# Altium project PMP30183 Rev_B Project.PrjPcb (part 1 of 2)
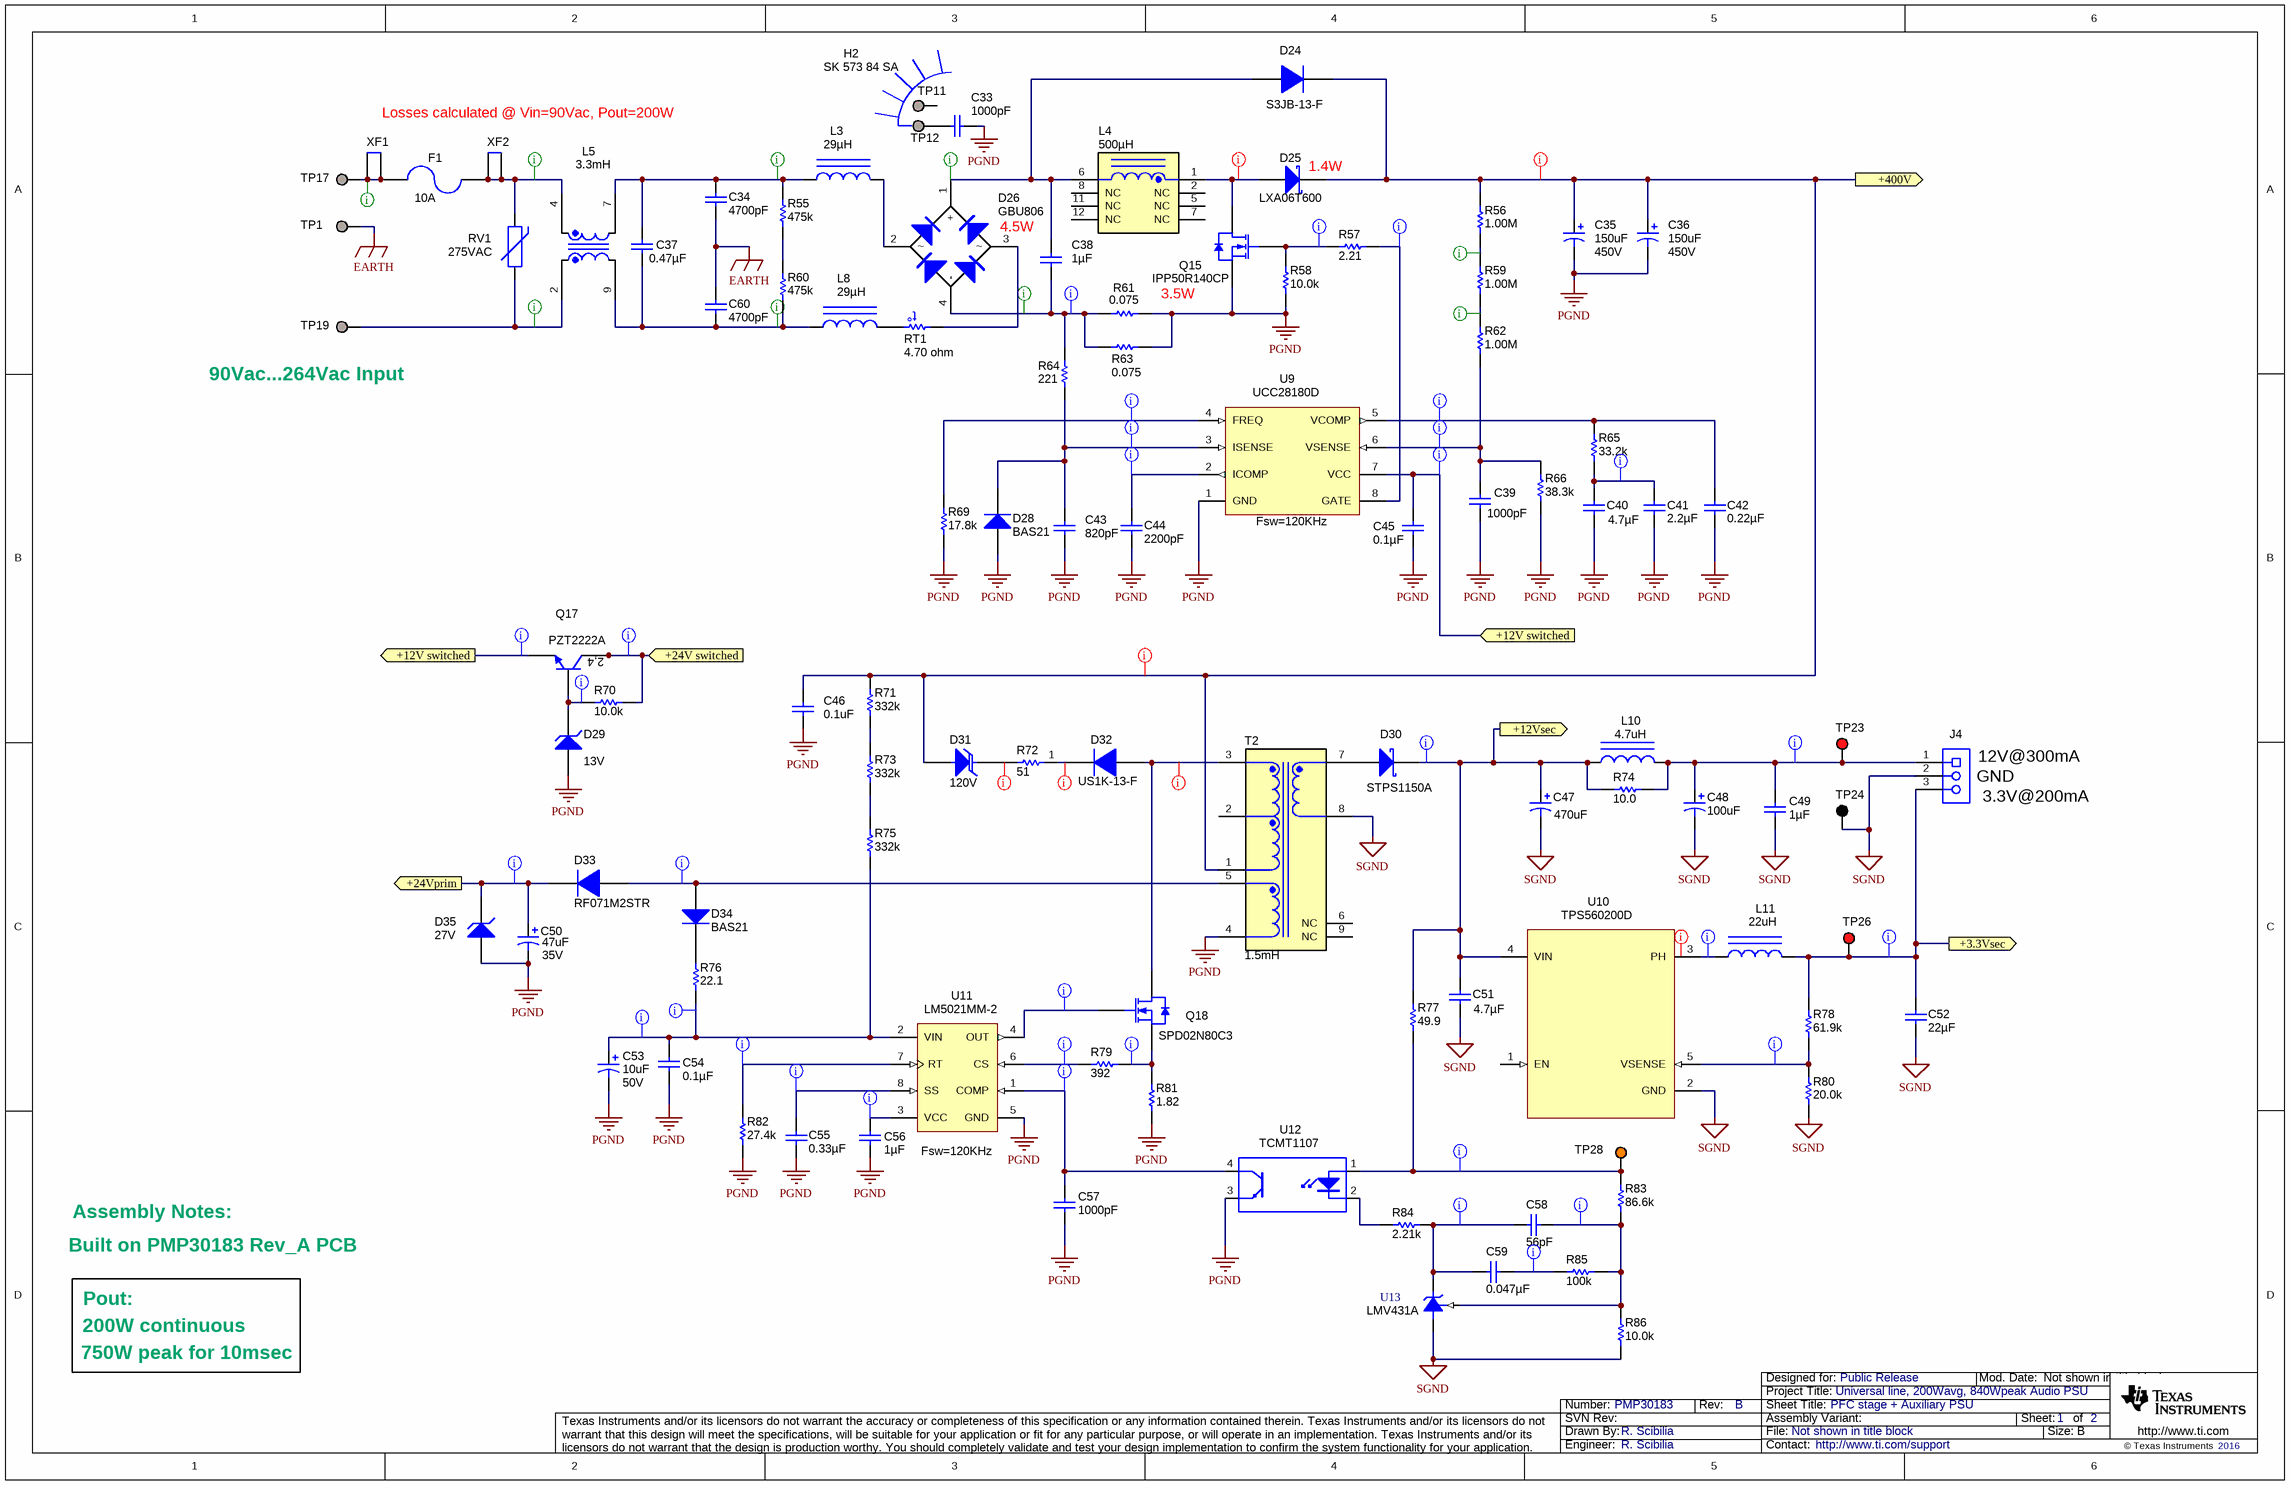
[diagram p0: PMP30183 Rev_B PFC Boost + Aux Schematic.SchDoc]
CopyrightYear: 2016; PCB_Layout: R. Scibilia; PCB_Rev: A; PRJ_Customer: Public Release; PRJ_Engineer: R. Scibilia; PRJ_Number: PMP30183; PRJ_Title: Universal line, 200Wavg, 840Wpeak Audio PSU; SCH_Rev: B; TechSupport: http://www.ti.com/support
2 sheets, 253 parts. Net scope: flat (ports and power ports of the same name join across sheets).
Board file: PMP30183 Rev_A PCB.PcbDoc
Sheets:
  PMP30183 Rev_B PFC Boost + Aux Schematic.SchDoc
  PMP30183 Rev_B 2-Switch Forward Schematic.SchDoc

## Sheet PMP30183 Rev_B PFC Boost + Aux Schematic.SchDoc: PFC stage + Auxiliary PSU
size 431 x 279 mm; Date: Not shown in title block; ApprovedBy: Not shown in title block; CheckedBy: Not shown in title block; Author: Not shown in title block; CompanyName: Not shown in title block; DrawnBy: R. Scibilia; Engineer: Not shown in title block; Organization: Not shown in title block; Address1: Not shown in title block; Address2: Not shown in title block; Address3: Not shown in title block; Address4: Not shown in title block; DocumentNumber: 2; Revision: Use project parameter SCH_Rev; SheetNumber: 1; SheetTotal: 2; PageSetup: Record=PageOptions¦CenterHorizontal=True¦CenterVertical=True¦PrintScale=0.96¦XCorrection=1.00¦YCorrection=1.00¦PrintKind=0¦BorderSize=5000000¦LeftOffset=0¦BottomOffset=0¦Orientation=2¦PaperLength=4200¦PaperWidth=2970¦Scale=100¦PaperSource=7¦PrintQuality=600¦MediaType=1¦DitherType=10¦PaperKind=A3¦PrintScaleMode=1; PRJ_Engineer: R. Scibilia; PRJ_Number: PMP30183

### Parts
C33  ValueDisplayed: 1000pF  [1206]  (hidden comment: GRM31BR72J102KW01L)
C34  ValueDisplayed: 4700pF  [VY2_1250x500x1650]  (hidden comment: VY2472M49Y5US63V7)
C35  value 150uF  Value2: 450V  [SMQ_2200X2500]  (hidden comment: 450MXK150MEFCSN22X30)
C36  value 150uF  Value2: 450V  [SMQ_2200X2500]  (hidden comment: 450MXK150MEFCSN22X30)
C37  ValueDisplayed: 0.47µF  [CAPRR2250W80L2550T850H1750]  (hidden comment: ECQ-U2A474ML)
C38  ValueDisplayed: 1µF  [CAPRR2250W80L2550T850H1750]  (hidden comment: R46KN410000P1M)
C39  ValueDisplayed: 1000pF  [0603]  (hidden comment: C1608X7R1H102K)
C40  ValueDisplayed: 4.7µF  [0805_HV]  (hidden comment: C2012X5R1E475K125AB)
C41  ValueDisplayed: 2.2µF  [0805_HV]  (hidden comment: C2012X7R1C225K)
C42  ValueDisplayed: 0.22µF  [0603]  (hidden comment: C1608X7R1C224K)
C43  ValueDisplayed: 820pF  [0603]  (hidden comment: C1608C0G1H821J)
C44  ValueDisplayed: 2200pF  [0603]  (hidden comment: C1608X7R1H222K)
C45  ValueDisplayed: 0.1µF  [0603]  (hidden comment: C1608X7R1H104K)
C46  value 0.1uF  [1210]  (hidden comment: C3225X7T2J104K160AC)
C47  value 470uF  [CAPPR3p5-8x16]  (hidden comment: EKZM160ELL471MHB5D)
C48  value 100uF  [ML_500x500]  (hidden comment: EKZM160ELL101ME11D)
C49  ValueDisplayed: 1µF  [0603]  (hidden comment: C1608X7R1C105K)
C50  value 47uF  Value2: 35V  [ZL_630x1100]  (hidden comment: UPW1V470MED1TD)
C51  ValueDisplayed: 4.7µF  [0805_HV]  (hidden comment: C2012X5R1E475K125AB)
C52  ValueDisplayed: 22µF  [0805_HV]  (hidden comment: C2012X5R0J226M)
C53  value 10uF  Value2: 50V  [ZLJ_500x1100]  (hidden comment: UPW1H100MDD)
C54  ValueDisplayed: 0.1µF  [0603]  (hidden comment: C1608X7R1H104K)
C55  ValueDisplayed: 0.33µF  [0603]  (hidden comment: C0603C334K4RACTU)
C56  ValueDisplayed: 1µF  [0603]  (hidden comment: C1608X7R1C105K)
C57  ValueDisplayed: 1000pF  [0603]  (hidden comment: C1608X7R1H102K)
C58  ValueDisplayed: 56pF  [0603]  (hidden comment: C1608C0G1H560J)
C59  ValueDisplayed: 0.047µF  [0603]  (hidden comment: C1608X8R1H473K)
C60  ValueDisplayed: 4700pF  [VY2_1250x500x1650]  (hidden comment: VY2472M49Y5US63V7)
D24  S3JB-13-F  [SMB]
D25  LXA06T600  [TO-220-F2]
D26  GBU806  [GBU]
D28  value BAS21  [SOT-23]  (hidden comment: BAS21-7-F)
D29  value 13V  [sod-323]  (hidden comment: MMSZ5243BS-7-F)
D30  STPS1150A  [SMA]
D31  value 120V  [SMA]  (hidden comment: SMAJ120A)
D32  US1K-13-F  [SMA]
D33  RF071M2STR  [SOD-123]
D34  value BAS21  [SOT-23]  (hidden comment: BAS21-7-F)
D35  value 27V  [SOD-123]  (hidden comment: MMSZ4711-T1G)
F1  value 10A  (hidden comment: 0216010.MXP)
H2  SK 573 84 SA  [FE_SK573_84]
J4  39357-0003  [Molex_39357-0003]  (value not drawn)
L3  ValueDisplayed: 29µH  [WE-FI_1900x1050]  (hidden comment: 7447016)
L4  ValueDisplayed: 500µH  [750316373]  (hidden comment: 750316373)
L5  value 3.3mH  [IND_WE-CMB_L]  (hidden comment: 744824433)
L8  ValueDisplayed: 29µH  [WE-FI_1900x1050]  (hidden comment: 7447016)
L10  value 4.7uH  [WE-PD2-S]  (hidden comment: 744773047)
L11  value 22uH  [WE-SPC_4838]  (hidden comment: 74408943220)
Q15  IPP50R140CP  [TO-220AB]
Q17  PZT2222A  [SOT-223]
Q18  value SPD02N80C3  [DPAK]  (hidden comment: SPD02N80C3ATMA1)
R55  ValueDisplayed: 475k  [1206]  (hidden comment: RC1206FR-07475KL)
R56  ValueDisplayed: 1.00M  [1206]  (hidden comment: CRCW12061M00FKEA)
R57  value 2.21  [0805_HV]  (hidden comment: CRCW08052R21FKEA)
R58  value 10.0k  [0603]  (hidden comment: CRCW060310K0FKEA)
R59  ValueDisplayed: 1.00M  [1206]  (hidden comment: CRCW12061M00FKEA)
R60  ValueDisplayed: 475k  [1206]  (hidden comment: RC1206FR-07475KL)
R61  ValueDisplayed: 0.075  [2512]  (hidden comment: CSRN2512FK75L0)
R62  ValueDisplayed: 1.00M  [1206]  (hidden comment: CRCW12061M00FKEA)
R63  ValueDisplayed: 0.075  [2512]  (hidden comment: CSRN2512FK75L0)
R64  value 221  [0603]  (hidden comment: CRCW0603221RFKEA)
R65  ValueDisplayed: 33.2k  [0603]  (hidden comment: CRCW060333K2FKEA)
R66  ValueDisplayed: 38.3k  [0603]  (hidden comment: CRCW060338K3FKEA)
R69  ValueDisplayed: 17.8k  [0603]  (hidden comment: CRCW060317K8FKEA)
R70  value 10.0k  [0603]  (hidden comment: CRCW060310K0FKEA)
R71  value 332k  [1206]  (hidden comment: CRCW1206332KFKEA)
R72  value 51  [0805_HV]  (hidden comment: CRCW080551R0JNEA)
R73  value 332k  [1206]  (hidden comment: CRCW1206332KFKEA)
R74  ValueDisplayed: 10.0  [0603]  (hidden comment: CRCW060310R0FKEA)
R75  value 332k  [1206]  (hidden comment: CRCW1206332KFKEA)
R76  ValueDisplayed: 22.1  [0603]  (hidden comment: CRCW060322R1FKEA)
R77  value 49.9  [0603]  (hidden comment: CRCW060349R9FKEA)
R78  ValueDisplayed: 61.9k  [0603]  (hidden comment: CRCW060361K9FKEA)
R79  ValueDisplayed: 392  [0603]  (hidden comment: CRCW0603392RFKEA)
R80  ValueDisplayed: 20.0k  [0603]  (hidden comment: CRCW060320K0FKEA)
R81  ValueDisplayed: 1.82  [1206]  (hidden comment: CRCW12061R82FKEA)
R82  ValueDisplayed: 27.4k  [0603]  (hidden comment: CRCW060327K4FKEA)
R83  ValueDisplayed: 86.6k  [0603]  (hidden comment: CRCW060386K6FKEA)
R84  value 2.21k  [0603]  (hidden comment: CRCW06032K21FKEA)
R85  ValueDisplayed: 100k  [0603]  (hidden comment: CRCW0603100KFKEA)
R86  value 10.0k  [0603]  (hidden comment: CRCW060310K0FKEA)
RT1  value 4.70 ohm  [S237]  (hidden comment: B57237S0479M000)
RV1  value 275VAC  [Epcos_B72220S0271K101]  (hidden comment: B72220S0271K101)
T2  ValueDisplayed: 1.5mH  [Wurth_7508110338]  (hidden comment: 7508110338)
TP1  TESTPOINT  [PAD_115mil-80milhole]  (value not drawn)  (no BOM)
TP11  TESTPOINT  [PAD_115mil-80milhole]  (value not drawn)  (no BOM)
TP12  TESTPOINT  [PAD_115mil-80milhole]  (value not drawn)  (no BOM)
TP17  TESTPOINT  [PAD_115mil-80milhole]  (value not drawn)  (no BOM)
TP19  TESTPOINT  [PAD_115mil-80milhole]  (value not drawn)  (no BOM)
TP23  5000  [Keystone5000]  (value not drawn)
TP24  5001  [Keystone5001]  (value not drawn)
TP26  5000  [Keystone5000]  (value not drawn)
TP28  5003  [Keystone5003]  (value not drawn)
U9  UCC28180D  [D0008A_N]
U10  value TPS560200D  [DBV0005A_N]  (hidden comment: TPS560200DBVR)
U11  value LM5021MM-2  [MUA08A_N]  (hidden comment: LM5021MMX-2)
U12  TCMT1107  [SOP-4]
U13  value LMV431A  [MF03A_N]  (hidden comment: LMV431BIMFX)
XF1  01000056Z  [Littelfuse_0100-0020_54_56]  (value not drawn)
XF2  01000056Z  [Littelfuse_0100-0020_54_56]  (value not drawn)

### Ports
+3.3Vsec, +12V switched, +12Vsec, +24V switched, +24Vprim, +400V

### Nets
EARTH: C34.1 C60.2 TP1.1
PGND: C33.1 C35.2(-) C36.2(-) C39.2 C40.2 C41.2 C42.2 C43.2 C44.2 C45.2 C46.2 C50.2(-) C53.2(-) C54.2 C55.2 C56.2 C57.2 D28.1(A) D29.2(A) D35.2(A) Q15.3(S) R58.1 R61.2 R63.2 R66.1 R69.1 R81.1 R82.1 T2.4 U9.1(GND) U11.5(GND) U12.3(E)
SGND: C47.2(-) C48.2(-) C49.2 C51.2 C52.2 J4.2 R80.1 R86.1 T2.8 TP24.1 U10.2(GND) U13.3(A)
+3.3Vsec: C52.1 J4.3 L11.2 R78.2 TP26.1 ; port +3.3Vsec
+12V switched: C45.1 Q17.3(E) U9.7(VCC) ; port +12V switched
+12Vsec: C47.1(+) C51.1 D30.1(K) L10.1 R74.1 R77.2 U10.4(VIN) ; port +12Vsec
+24V switched: Q17.2(C) Q17.4(C) R70.1 ; port +24V switched
+24Vprim: C50.1(+) D33.1(K) D35.1(K) ; port +24Vprim
+400V: C35.1(+) C36.1(+) C46.1 D24.1(K) D25.1(K) D31.2(A) R56.2 R71.2 T2.1 ; port +400V
NetC33_2: C33.2 TP12.1
NetC34_2: C34.2 C37.1 L3.1 L5.7 R55.2
NetC37_2: C37.2 C60.1 L5.9 L8.1 R60.1
NetC38_1: C38.1 D24.2(A) D26.1(+) L4.6
NetC38_2: C38.2 D26.4(-) R61.1 R63.1 R64.2
NetC39_1: C39.1 R62.1 R66.2 U9.6(VSENSE)
NetC40_1: C40.1 C41.1 R65.1
NetC42_1: C42.1 R65.2 U9.5(VCOMP)
NetC43_1: C43.1 D28.3(K) R64.1 U9.3(ISENSE)
NetC44_1: C44.1 U9.2(ICOMP)
NetC48_1: C48.1(+) C49.1 J4.1 L10.2 R74.2 TP23.1
NetC53_1: C53.1(+) C54.1 R75.1 R76.2 U11.2(VIN)
NetC55_1: C55.1 U11.8(SS)
NetC56_1: C56.1 U11.3(VCC)
NetC57_1: C57.1 U11.1(COMP) U12.4(C)
NetC58_1: C58.1 R83.1 R85.1 R86.2 U13.1(REF)
NetC58_2: C58.2 C59.2 R84.1 U13.2(K)
NetC59_1: C59.1 R85.2
NetD25_2: D25.2(A) L4.1 Q15.2(D)
NetD26_2: D26.2 L3.2
NetD26_3: D26.3 RT1.1
NetD29_1: D29.1(K) Q17.1(B) R70.2
NetD30_2: D30.2(A) T2.7
NetD31_1: D31.1(K) R72.2
NetD32_1: D32.1(K) R72.1
NetD32_2: D32.2(A) Q18.4(D) T2.3
NetD33_2: D33.2(A) D34.1(A) T2.5
NetD34_3: D34.3(K) R76.1
NetF1_1: F1.1 L5.4 RV1.2 XF2.1 XF2.2
NetF1_2: F1.2 TP17.1 XF1.1 XF1.2
NetL5_2: L5.2 RV1.1 TP19.1
NetL8_2: L8.2 RT1.2
NetL11_1: L11.1 U10.3(PH)
NetQ15_1: Q15.1(G) R57.1 R58.2
NetQ18_1: Q18.1(G) U11.4(OUT)
NetQ18_3: Q18.3(S) R79.2 R81.2
NetR55_1: R55.1 R60.2
NetR56_1: R56.1 R59.2
NetR57_2: R57.2 U9.8(GATE)
NetR59_1: R59.1 R62.2
NetR69_2: R69.2 U9.4(FREQ)
NetR71_1: R71.1 R73.2
NetR73_1: R73.1 R75.2
NetR77_1: R77.1 R83.2 TP28.1 U12.1(A)
NetR78_1: R78.1 R80.2 U10.5(VSENSE)
NetR79_1: R79.1 U11.6(CS)
NetR82_2: R82.2 U11.7(RT)
NetR84_2: R84.2 U12.2(K)

Not connected (* = marked no-connect by the designer): L4 2(NC) 5(NC) 7(NC) 8(NC) 11(NC) 12(NC); T2 2 6(NC) 9(NC); TP11 1; U10 1(EN)

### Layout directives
rule Undefined; rule Clearance Constraint [Clearance = 30mil]: +400V, NetD25_2, NetD31_1, NetD32_1, NetD32_2
rule Undefined; rule Clearance Constraint [Clearance = 10mil]: (no net found under the mark), +3.3Vsec, +12V switched, +12Vsec, +24V switched, +24Vprim, NetC38_2, NetC39_1, NetC40_1, NetC42_1, NetC43_1, NetC44_1, NetC48_1, NetC53_1, NetC55_1, NetC56_1, NetC57_1, NetC58_1, NetC58_2, NetC59_1, NetD29_1, NetD33_2, NetL11_1, NetQ15_1, NetQ18_1, NetQ18_3, NetR57_2, NetR69_2, NetR77_1, NetR78_1, NetR79_1, NetR82_2
rule Undefined; rule Clearance Constraint [Clearance = 20mil]: NetC34_2, NetC37_2, NetC38_1, NetC38_2, NetF1_1, NetF1_2, NetL5_2, NetR56_1, NetR59_1

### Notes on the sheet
- Losses calculated @ Vin=90Vac, Pout=200W
- (near D25) 1.4W
- (near D26) 4.5W
- (near R61) 3.5W
- (near TP19) 90Vac...264Vac Input
- (near U9) Fsw=120KHz
- (near J4) 12V@300mA
- (near J4) GND
- (near J4) 3.3V@200mA
- (near U11) Fsw=120KHz
- Assembly Notes:
- Built on PMP30183 Rev_A PCB
- Pout:
- 200W continuous
- 750W peak for 10msec

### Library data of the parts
C33 = GRM31BR72J102KW01L: CAP, CERM, 1000 pF, 630 V, +/- 10%, X7R, 1206; Manufacturer: MuRata; Polarized: N; CompType: Capacitor; Value: 1000pF; U/M: EA; Cap_F: 0.000000001; Tolerance_%: 10; Value1: Unknown; VDC_V: 630; Value2: 630V; TaMin_C: -55; TaMax_C: 125; SizeArea_mm2: 5.12; SizeAreaWB_mm2: 10.92; SizeX_mm: 3.2; SizeY_mm: 1.6; SizeZ_mm: 1.35; AEC Category: Q200
C34 C60 = VY2472M49Y5US63V7: CAP, CERM, 4700 pF, 440 V, +/- 20%, Y5U, TH, 12.5x5mm; Manufacturer: Vishay-Bccomponents; Polarized: N; CompType: Capacitor; Value: 4700pF; U/M: EA; Cap_F: 0.0000000047; Tolerance_%: 20; Value1: Unknown; VDC_V: 440; Value2: 440V; TaMin_C: -40; TaMax_C: 125; Cap_Case: 12.5x5x16.5
C35 C36 = ESMQ451VSN101MP25S: CAP, AL, 150 µF, 450 V, +/- 20%, TH; Manufacturer: Rubycon; Polarized: Y; CompType: Capacitor; ValueDisplayed: 150µF; U/M: EA; Cap_F: 0.00015; Tolerance_%: 20; Value1: Unknown; VDC_V: 450; IRMS_A: 1.12; TaMin_C: -25; TaMax_C: 105; Cap_Case: 22x25; AEC Category: Q200
C37 = ECQ-U2A474ML: CAP, Film, 0.47 µF, 275 V, +/- 20%, TH; Manufacturer: Panasonic; Polarized: N; CompType: Capacitor; Value: 0.47uF; U/M: EA; Cap_F: 0.00000047; Tolerance_%: 20; Value1: Unknown; VDC_V: 275; Value2: 275V; TaMin_C: -40; TaMax_C: 100; Cap_Case: Radial 25x8.5x18.5
C38 = ECQ-U2A474ML: CAP, Film, 1 µF, 275 V, +/- 20%, TH; Manufacturer: Kemet; Polarized: N; CompType: Capacitor; Value: 1uF; U/M: EA; Cap_F: 0.00000047; Tolerance_%: 20; Value1: Unknown; VDC_V: 275; Value2: 275V; TaMin_C: -40; TaMax_C: 100; Cap_Case: Radial 25x8.5x18.5
C39 C57 = C1608X7R1H102K: CAP, CERM, 1000 pF, 50 V, +/- 10%, X7R, 0603; Manufacturer: TDK; Polarized: N; CompType: Capacitor; Value: 1000pF; U/M: EA; Cap_F: 0.000000001; Tolerance_%: 10; ESR_ohm: 0.24; Value1: 0.24 ohm; VDC_V: 50; Value2: 50V; TaMin_C: -55; TaMax_C: 125
C40 C51 = C2012X5R1E475K125AB: CAP, CERM, 4.7 µF, 25 V, +/- 10%, X5R, 0805; Manufacturer: TDK; Polarized: N; CompType: Capacitor; Value: 4.7uF; U/M: EA; Cap_F: 0.0000047; Tolerance_%: 10; Value1: Unknown; VDC_V: 25; Value2: 25V; TaMin_C: -55; TaMax_C: 85; Cap_Case: 0805
C41 = C2012X7R1C225K: CAP, CERM, 2.2 µF, 16 V, +/- 10%, X7R, 0805; Manufacturer: TDK; Polarized: N; CompType: Capacitor; Value: 2.2uF; U/M: EA; Cap_F: 0.0000022; Tolerance_%: 10; ESR_ohm: 0.0049; Value1: 0.0049 ohm; VDC_V: 16; Value2: 16V; TaMin_C: -55; TaMax_C: 125; Cap_Case: 0805
C42 = C1608X7R1C224K: CAP, CERM, 0.22 µF, 16 V, +/- 10%, X7R, 0603; Manufacturer: TDK; Polarized: N; CompType: Capacitor; Value: 0.22uF; U/M: EA; Cap_F: 0.00000022; Tolerance_%: 10; ESR_ohm: 0.0125; Value1: 0.0125 ohm; VDC_V: 16; Value2: 16V; TaMin_C: -55; TaMax_C: 125
C43 = C1608C0G1H821J: CAP, CERM, 820pF, 50V, +/-5%, C0G/NP0, 0603; Manufacturer: TDK; Polarized: N; CompType: Capacitor; U/M: EA; Cap_F: 0.00000000082; Tolerance_%: 5; ESR_Ohm: 0.0482; Value1: 0.0482 ohm; VDC_V: 50; TaMin_C: -55; TaMax_C: 125
C44 = C1608X7R1H222K: CAP, CERM, 2200 pF, 50 V, +/- 10%, X7R, 0603; Manufacturer: TDK; Polarized: N; CompType: Capacitor; Value: 2200pF; U/M: EA; Cap_F: 0.0000000022; Tolerance_%: 10; ESR_ohm: 0.145; Value1: 0.145 ohm; VDC_V: 50; Value2: 50V; TaMin_C: -55; TaMax_C: 125
C45 C54 = C1608X7R1H104K: CAP, CERM, 0.1uF, 50V, +/-10%, X7R, 0603; Manufacturer: TDK; Polarized: N; CompType: Capacitor; U/M: EA; Cap_F: 0.0000001; Tolerance_%: 10; ESR_Ohm: 0.017; Value1: 0.017 ohm; VDC_V: 50; TaMin_C: -55; TaMax_C: 125
C46 = GRM32DR72J473KW01L: CAP, CERM, 0.1 µF, 630 V, +/- 10%, X7T 1210; Manufacturer: TDK; Polarized: N; CompType: Capacitor; ValueDisplayed: 0.1µF; U/M: EA; Cap_F: 0.000000047; Tolerance_%: 10; Value1: Unknown; VDC_V: 630; Value2: 630V; TaMin_C: -55; TaMax_C: 125
C47 = ESY477M016AG8AA: CAP, AL, 470uF, 16V, +/-20%, TH; Manufacturer: Nippon Chemi-Con; Polarized: Y; CompType: Capacitor; ValueDisplayed: 470µF; U/M: EA; Cap_F: 0.00047; Tolerance_%: 20; Value1: Unknown; VDC_V: 16; TaMin_C: -40; TaMax_C: 105; Cap_Case: 8x16
C48 = 25ML22MEFC5X5: CAP, AL, 100 µF, 16 V, +/- 20%, TH; Manufacturer: Nippon Chemi-Con; Polarized: Y; CompType: Capacitor; ValueDisplayed: 22µF; U/M: EA; Cap_F: 0.000022; Tolerance_%: 20; Value1: Unknown; VDC_V: 25; Value2: 16V; IRMS_A: 0.042; TaMin_C: -40; TaMax_C: 105; Cap_Case: 5x5
C49 C56 = C1608X7R1C105K: CAP, CERM, 1uF, 16V, +/-10%, X7R, 0603; Manufacturer: TDK; Polarized: N; CompType: Capacitor; U/M: EA; Cap_F: 0.000001; Tolerance_%: 10; ESR_Ohm: 0.0057; Value1: 0.0057 ohm; VDC_V: 16; TaMin_C: -55; TaMax_C: 125
C50 = 35ZL56MEFCTA6.3X11: CAP, AL, 47 µF, 35 V, +/- 20%, 0.25 ohm, TH; Manufacturer: Nichicon; Polarized: Y; CompType: Capacitor; ValueDisplayed: 47µF; U/M: EA; Cap_F: 0.000056; Tolerance_%: 20; VDC_V: 35; ESR_ohm: 0.25; IRMS_A: 0.405; TaMin_C: -40; TaMax_C: 105; Cap_Case: 6.3x11; AEC Category: Q200; AEC Qualified: N
C52 = C2012X5R0J226M: CAP, CERM, 22 µF, 6.3 V, +/- 20%, X5R, 0805; Manufacturer: TDK; Polarized: N; CompType: Capacitor; Value: 22uF; U/M: EA; Cap_F: 0.000022; Tolerance_%: 20; ESR_ohm: 0.0018; Value1: 0.0018 ohm; VDC_V: 6.3; Value2: 6.3V; TaMin_C: -55; TaMax_C: 85; Cap_Case: 0805
C53 = 35ZLJ47MTA5X11: CAP, AL, 10 µF, 50 V, +/- 20%, 1.4 ohm, TH; Manufacturer: Nichicon; Polarized: Y; CompType: Capacitor; ValueDisplayed: 10µF; U/M: EA; Cap_F: 0.000047; Tolerance_%: 20; Value1: 1.4 ohm; VDC_V: 35; ESR_ohm: 0.4; IRMS_A: 0.45; TaMin_C: -40; TaMax_C: 105; Cap_Case: 5x11mm; AEC Category: Q200; AEC Qualified: N
C55 = C0603C334K4RACTU: CAP, CERM, 0.33 µF, 16 V, +/- 10%, X7R, 0603; Manufacturer: Kemet; Polarized: N; CompType: Capacitor; Value: 0.33uF; U/M: EA; Cap_F: 0.00000033; Tolerance_%: 10; Value1: Unknown; VDC_V: 16; Value2: 16V; TaMin_C: -55; TaMax_C: 125; AEC Category: Q200
C58 = C1608C0G1H560J: CAP, CERM, 56pF, 50V, +/-5%, C0G/NP0, 0603; Manufacturer: TDK; Polarized: N; CompType: Capacitor; U/M: EA; Cap_F: 0.000000000056; Tolerance_%: 5; ESR_Ohm: 0.2; Value1: 0.2 ohm; VDC_V: 50; TaMin_C: -55; TaMax_C: 125
C59 = C1608X8R1H473K: CAP, CERM, 0.047 µF, 50 V, +/- 10%, X8R, 0603; Manufacturer: TDK; Polarized: N; CompType: Capacitor; Value: 0.047uF; U/M: EA; Cap_F: 0.000000047; Tolerance_%: 10; ESR_ohm: 0.0198; Value1: 0.0198 ohm; VDC_V: 50; Value2: 50V; TaMin_C: -55; TaMax_C: 150; AEC Category: Q200
D24 = MURS140-13-F: Diode, Standard, 600 V, 3 A, SMB; Manufacturer: Diodes Inc.; U/M: EA; Vf_V: 1.25; Value1: 1A; Value2: 1.25V; Io_A: 1; Vr_V: 600; TJmax_C: 150; RJC_CperW: 13; SizeAreaWB_mm2: 44.156; SizeArea_mm2: 21.336; SizeX_mm: 5.6; SizeY_mm: 3.81; SizeZ_mm: 2.6; AEC Category: Q101
D25 = C3D04060A: Diode, X-Series PFC, 600 V, 6 A, TH; Manufacturer: Power Integrations; U/M: EA; Vf_V: 1.8; Value1: 6A; Value2: 1.8V; Io_A: 6; Vr_V: 600; TJmax_C: 175; RJC_CperW: 11.5; Type: Schottky
D26 = GBU8005: Diode, Switching-Bridge, 600 V, 8 A, TH; Manufacturer: Diodes Inc.; U/M: EA; Vf_V: 1; Value1: 8A; Value2: 1V; Io_A: 8; Vr_V: 600; TJmax_C: 150; RJC_CperW: 2.2
D28 D34 = BAS21-7-F: Diode, Switching, 200 V, 0.2 A, SOT-23; Manufacturer: Diodes Inc.; U/M: EA; Vf_V: 1.25; Value1: 0.2A; Value2: 1.25V; Io_A: 0.2; Vr_V: 200; TJmax_C: 150; RJC_CperW: 500
D29 = MMSZ5243BS-7-F: Diode, Zener, 13 V, 200 mW, SOD-323; Manufacturer: Diodes Inc.; SymbolCreator: a0412235; U/M: EA; Power_W: 0.2; Vz_V: 13; Value1: 0.2W; RJA_CperW: 350
D30 = STPS130A: Diode, Schottky, 150 V, 1 A, SMA; Manufacturer: ST Microelectronics; U/M: EA; Vf_V: 0.46; Value1: 1A; Value2: 0.46V; Io_A: 1; Vr_V: 30; TJmax_C: 150
D31 = SMAJ120A: Diode, TVS, Uni, 120 V, 400 W, SMA; Manufacturer: Littelfuse; U/M: EA; Power_W: 400; Vr_V: 120; Value1: 400W
D32 = US1K-13-F: Diode, Fast Rectifier, 800 V, 1 A, SMA; Manufacturer: Diodes Inc.; U/M: EA; Vf_V: 1.7; Value1: 1A; Value2: 1.7V; Io_A: 1; Vr_V: 800; TJmax_C: 150
D33 = RF071M2S: Diode, Ultrafast, 200 V, 1 A, SOD-123; Manufacturer: Rohm; U/M: EA; Vf_V: 0.85; Value1: 1A; Value2: 0.85V; Io_A: 1; Vr_V: 200; TJmax_C: 150
D35 = MMSZ4711-V: Diode, Zener, 27 V, 500 mW, SOD-123; Manufacturer: Vishay-Semiconductor; SymbolCreator: a0412235; U/M: EA; Power_W: 0.5; Vz_V: 27; Value1: 0.5W; RJA_CperW: 67; AEC Category: Q101
F1 = BK/S501-2-R: Fuse, 10 A, Fast Acting, 250 V, TH; Manufacturer: Littlefuse Inc; U/M: EA; VDC_V: 250; Interrupt_AC: 1500; Irating_A: 2; Vdrop: 0.205
H2 = SK 573 84 SA: Heat Sink, 25x30x84mm, for THFU 1-3+6+7, profile threads; Manufacturer: Fischer Elektronik; SymbolCreator: a0412235
J4 = 39357-0003: Terminal Block, 3.5 mm, 3x1, Tin, TH; Manufacturer: Molex; SymbolCreator: a0412235; U/M: EA
L3 L8 = 7447016: Inductor, Toroid, Ferrite, 29 µH, 7.8 A, 0.015 ohm, TH; Manufacturer: Wurth Elektronik; Value: 29uH; Ind_H: 29.0E-6; Imax_A: 7.8; Irms: 7.8A @ 40C rise; DCR_ohm: 0.015; Value2: 7.8A; SizeAreaWB_mm2: 262.5; SizeArea_mm2: 199.5; SizeX_mm: 19; SizeY_mm: 10.5; AEC Category: Q200; AEC Qualified: N
L4 = 750316373: Inductor, 500 µH, 0.03 ohm, TH; Manufacturer: Wurth Elektronik; SymbolCreator: Altium; Ind_H: 500.0E-6; Value: 500uH; DCR_ohm: 0.03; Value2: A; SizeAreaWB_mm2: 1369; SizeArea_mm2: 1225; SizeX_mm: 35; SizeZ_mm: 32; AEC Category: Q200; AEC Qualified: N
L5 = 744824310: Coupled inductor, 3.3 mH, 4 A, 0.035 ohm, +/- 30%, TH; Manufacturer: Wurth Elektronik eiSos; SymbolCreator: a0799628; Ind_H: 2.20E-3; DCR_ohm: 0.035; Isat: 6; Tolerance_%: 30
L10 = 744773047: Inductor, Shielded Drum Core, Ferrite, 4.7 µH, 1.82 A, 0.11 ohm, SMD; Manufacturer: Wurth Elektronik; Ind_H: 4.7E-6; ValueDisplayed: 4.7µH; Imax_A: 1.82; Irms: 1.82A @ 40C rise; Isat: 2.46A @ 10% inductance drop; DCR_ohm: 0.11; Value2: 1.82A
L11 = 74408943220: Inductor, Shielded Drum Core, Ferrite, 22 µH, 1.1 A, 0.185 ohm, SMD; Manufacturer: Wurth Elektronik; Ind_H: 22.0E-6; ValueDisplayed: 22µH; Imax_A: 1.1; Irms: 1.1A @ 40C rise; Isat: 1.4A @ 35% inductance drop; DCR_ohm: 0.185; Value2: 1.1A
Q15 = IPP50R199CP: MOSFET, N-CH, 550 V, 23 A, TO-220AB; Manufacturer: Infineon Technologies; Alternate Manufacturer: None; U/M: EA; ChType: N; VdsMax_V: 550; Value1: ? ohm; Rdson45_ohm: 0; Value2: 34 nC; QgTyp_nC: 34; Vgs_V: 20; IdsMax_A: 17
Q17 = PZT2222A, Fairchild Semiconductor: Transistor, NPN, 40 V, 0.5 A, SOT-223; CompType: BJT; PNP: 0; NPN: 1; Vceo_V: 40; IcRated_A: 0.5; Value1: 0.5 A; HfeMax: 300; TaMin_C: -55; TaMax_C: 150; U/M: EA
Q18 = SPD04N80C3: MOSFET, N-CH, 800 V, 2 A, DPAK; Manufacturer: Infineon Technologies; Alternate Manufacturer: None; U/M: EA; ChType: N; VdsMax_V: 800; Value1: 2.7 ohm; Rdson45_ohm: 1.3; Value2: 12 nC; QgTyp_nC: 12; Vgs_V: 3.9; IdsMax_A: 4
R55 R60 = RC1206FR-07475KL: RES, 475 k, 1%, 0.25 W, 1206; Manufacturer: Yageo America; CompType: Resistor; Value: 475k; Res_ohm: 475000; Tolerance_%: 1; Power_W: 0.25; Value2: 0.25W; VDC_V: 200; TempCo: 100 ppm/C; SizeArea_mm2: 5.12; SizeX_mm: 3.2; SizeY_mm: 1.6; SizeZ_mm: 1.35; EIA_Code: E96; U/M: EA; AEC Category: Q200
R56 R59 R62 = CRCW12061M00FKEA: RES, 1.00 M, 1%, 0.25 W, 1206; Manufacturer: Vishay-Dale; CompType: Resistor; Value: 1.00Meg; Res_ohm: 1000000; Value_Code: 1M00; Tolerance_%: 1; Power_W: 0.25; Value2: 0.25W; VDC_V: 200; TempCo: 100 ppm/C; EIA_Code: E96; U/M: EA
R57 = CRCW08052R21FKEA: RES, 2.21 ohm, 1%, 0.125W, 0805; Manufacturer: Vishay-Dale; CompType: Resistor; Value_Code: 2R21; Tolerance_%: 1; Power_W: 0.125; VDC_V: 150; TempCo: 100 ppm/C; EIA_Code: E96; U/M: EA
R58 R70 R86 = CRCW060310K0FKEA: RES, 10.0k ohm, 1%, 0.1W, 0603; Manufacturer: Vishay-Dale; CompType: Resistor; Res_ohm: 10000; Value_Code: 10k0; Tolerance_%: 1; Power_W: 0.1; VDC_V: 75; TempCo: 100 ppm/C; EIA_Code: E96; U/M: EA
R61 R63 = CSRN2512FK75L0: RES, 0.075, 1%, 2 W, 2512; Manufacturer: Stackpole Electronics Inc; CompType: Resistor; Value: 0.075; Value_Code: R075; Tolerance_%: 1; Power_W: 2; Value2: 2W; TempCo: 200 ppm/C; EIA_Code: E96; U/M: EA; AEC Category: Q200
R64 = CRCW0603221RFKEA: RES, 221 ohm, 1%, 0.1W, 0603; Manufacturer: Vishay-Dale; CompType: Resistor; Value_Code: 221R; Tolerance_%: 1; Power_W: 0.1; VDC_V: 75; TempCo: 100 ppm/C; EIA_Code: E96; U/M: EA
R65 = CRCW060333K2FKEA: RES, 33.2 k, 1%, 0.1 W, 0603; Manufacturer: Vishay-Dale; CompType: Resistor; Value: 33.2k; Res_ohm: 33200; Value_Code: 33k2; Tolerance_%: 1; Power_W: 0.1; Value2: 0.1W; VDC_V: 75; TempCo: 100 ppm/C; EIA_Code: E96; U/M: EA
R66 = CRCW060338K3FKEA: RES, 38.3 k, 1%, 0.1 W, 0603; Manufacturer: Vishay-Dale; CompType: Resistor; Value: 38.3k; Res_ohm: 38300; Value_Code: 38k3; Tolerance_%: 1; Power_W: 0.1; Value2: 0.1W; VDC_V: 75; TempCo: 100 ppm/C; EIA_Code: E96; U/M: EA
R69 = CRCW060317K8FKEA: RES, 17.8 k, 1%, 0.1 W, 0603; Manufacturer: Vishay-Dale; CompType: Resistor; Value: 17.8k; Res_ohm: 17800; Value_Code: 17k8; Tolerance_%: 1; Power_W: 0.1; Value2: 0.1W; VDC_V: 75; TempCo: 100 ppm/C; EIA_Code: E96; U/M: EA
R71 R73 R75 = CRCW1206332KFKEA: RES, 332k ohm, 1%, 0.25W, 1206; Manufacturer: Vishay-Dale; CompType: Resistor; Res_ohm: 332000; Tolerance_%: 1; Power_W: 0.25; VDC_V: 200; TempCo: 100 ppm/C; EIA_Code: E96; U/M: EA
R72 = CRCW080551R0JNEA: RES, 51 ohm, 5%, 0.125W, 0805; Manufacturer: Vishay-Dale; CompType: Resistor; Value_Code: 51R0; Tolerance_%: 5; Power_W: 0.125; VDC_V: 150; TempCo: 200 ppm/C; EIA_Code: E24; U/M: EA
R74 = CRCW060310R0FKEA: RES, 10.0, 1%, 0.1 W, 0603; Manufacturer: Vishay-Dale; CompType: Resistor; Value: 10.0; Res_ohm: 10; Value_Code: 10R0; Tolerance_%: 1; Power_W: 0.1; Value2: 0.1W; VDC_V: 75; TempCo: 100 ppm/C; EIA_Code: E96; U/M: EA
R76 = CRCW060322R1FKEA: RES, 22.1, 1%, 0.1 W, 0603; Manufacturer: Vishay-Dale; CompType: Resistor; Value: 22.1; Value_Code: 22R1; Tolerance_%: 1; Power_W: 0.1; Value2: 0.1W; VDC_V: 75; TempCo: 100 ppm/C; EIA_Code: E96; U/M: EA
R77 = CRCW060349R9FKEA: RES, 49.9 ohm, 1%, 0.1W, 0603; Manufacturer: Vishay-Dale; CompType: Resistor; Value_Code: 49R9; Tolerance_%: 1; Power_W: 0.1; VDC_V: 75; TempCo: 100 ppm/C; EIA_Code: E96; U/M: EA
R78 = CRCW060361K9FKEA: RES, 61.9 k, 1%, 0.1 W, 0603; Manufacturer: Vishay-Dale; CompType: Resistor; Value: 61.9k; Res_ohm: 61900; Value_Code: 61k9; Tolerance_%: 1; Power_W: 0.1; Value2: 0.1W; VDC_V: 75; TempCo: 100 ppm/C; EIA_Code: E96; U/M: EA
R79 = CRCW0603392RFKEA: RES, 392, 1%, 0.1 W, 0603; Manufacturer: Vishay-Dale; CompType: Resistor; Value: 392; Value_Code: 392R; Tolerance_%: 1; Power_W: 0.1; Value2: 0.1W; VDC_V: 75; TempCo: 100 ppm/C; EIA_Code: E96; U/M: EA
R80 = CRCW060320K0FKEA: RES, 20.0 k, 1%, 0.1 W, 0603; Manufacturer: Vishay-Dale; CompType: Resistor; Value: 20.0k; Res_ohm: 20000; Value_Code: 20k0; Tolerance_%: 1; Power_W: 0.1; Value2: 0.1W; VDC_V: 75; TempCo: 100 ppm/C; EIA_Code: E96; U/M: EA
R81 = CRCW12061R82FKEA: RES, 1.82, 1%, 0.25 W, 1206; Manufacturer: Vishay-Dale; CompType: Resistor; Value: 1.82; Value_Code: 1R82; Tolerance_%: 1; Power_W: 0.25; Value2: 0.25W; VDC_V: 200; TempCo: 100 ppm/C; EIA_Code: E96; U/M: EA
R82 = CRCW060327K4FKEA: RES, 27.4 k, 1%, 0.1 W, 0603; Manufacturer: Vishay-Dale; CompType: Resistor; Value: 27.4k; Res_ohm: 27400; Value_Code: 27k4; Tolerance_%: 1; Power_W: 0.1; Value2: 0.1W; VDC_V: 75; TempCo: 100 ppm/C; EIA_Code: E96; U/M: EA; AEC Category: Q200
R83 = CRCW060386K6FKEA: RES, 86.6 k, 1%, 0.1 W, 0603; Manufacturer: Vishay-Dale; CompType: Resistor; Value: 86.6k; Res_ohm: 86600; Value_Code: 86k6; Tolerance_%: 1; Power_W: 0.1; Value2: 0.1W; VDC_V: 75; TempCo: 100 ppm/C; EIA_Code: E96; U/M: EA
R84 = CRCW06032K21FKEA: RES, 2.21k ohm, 1%, 0.1W, 0603; Manufacturer: Vishay-Dale; CompType: Resistor; Res_ohm: 2210; Value_Code: 2k21; Tolerance_%: 1; Power_W: 0.1; VDC_V: 75; TempCo: 100 ppm/C; EIA_Code: E96; U/M: EA
R85 = CRCW0603100KFKEA: RES, 100 k, 1%, 0.1 W, 0603; Manufacturer: Vishay-Dale; CompType: Resistor; Value: 100k; Res_ohm: 100000; Tolerance_%: 1; Power_W: 0.1; Value2: 0.1W; VDC_V: 75; TempCo: 100 ppm/C; EIA_Code: E96; U/M: EA
RT1 = B57237S0479M000: Thermistor NTC, 4.70 ohm, 20%, 15x7mm; Manufacturer: TDK; Tolerance_%: 20; Power_W: 3.1; TaMin_C: -55; TaMax_C: 170; U/M: EA
RV1 = B72220S0271K101: Varistor 275 VAC, 100 A, TH; Manufacturer: TDK; SymbolCreator: a0412235
T2 = 7508110338: Transformer, 1.5 mH, TH; Manufacturer: Wurth Elektronik; SymbolCreator: Altium; Value: 1.5mH; Lp: 1500; DCR_ohm: 1.76; Ns1toNp: 0.128; Rs1: 0.05; SizeAreaWB_mm2: 588.8016; SizeArea_mm2: 495.4016; SizeX_mm: 24.38; SizeY_mm: 20.32; SizeZ_mm: 16
TP1 TP11 TP12 TP17 TP19 = PAD_115mil-80milhole: 115mil pad, 80mil hole; Manufacturer: Any
TP23 TP26 = 5000: Test Point, Miniature, Red, TH; Manufacturer: Keystone; CompType: Test Point Loop; U/M: EA
TP24 = 5001: Test Point, Miniature, Black, TH; Manufacturer: Keystone; CompType: Test Point Loop; U/M: EA
TP28 = 5003: Test Point, Miniature, Orange, TH; Manufacturer: Keystone; CompType: Test Point Loop; U/M: EA
U9 = UCC28180D: 8-PIN CONTINUOUS CONDUCTION MODE (CCM) PFC CONTROLLER, D0008A; Manufacturer: Texas Instruments; SymbolCreator: a0411947; CompType: IC; U/M: EA
U10 = TPS560200DBV: 4.5V to 18V Input, 500mA Synchronous Step Down SWIFT Converter with Advanced Eco-mode, DBV0005A; Manufacturer: Texas Instruments; SymbolCreator: a0411947; CompType: IC; U/M: EA
U11 = LM5021MMX-2: AC-DC Current Mode PWM Controller, 8-pin MSOP; PartNumber: LM5021MM-2/NOPB; Manufacturer: Texas Instruments; PackageTopMarking: ZXTT*21-2; PowerWise: N; CompType: Switcher
U12 = TCMT1107: Optocoupler, 3.75 kV, 80-160% CTR, SMD-4; Manufacturer: Vishay-Semiconductor; CTR_Min: 80% @ 5mA; CTR_Max: 160% @ 5mA; Voltage_Isolation_Vrms: 3750; tr_typ: 4us; tf_typ: 4.7us; U/M: EA
U13 = LMV431BIMFX: Low-Voltage (1.24V) Adjustable Precision Shunt Regulators, 3-pin SOT-23; PartNumber: LMV431AIMFX/NOPB; Manufacturer: National Semiconductor; PackageTopMarking: RLB*XTT; PowerWise: N; CompType: MiscPower
XF1 XF2 = 01000056Z: Fuse Holder, 10A, TH; Manufacturer: Littelfuse; SymbolCreator: a0411947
